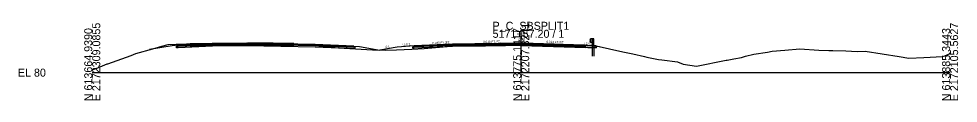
# Model space of a CAD drawing. Extents: x -26 to 1303, y -3010 to 12023.
# Drawn here: x -25.7 to 302.8, y -9.7 to 17.8 of the extents above; entities that cross this region are included whole.
import ezdxf

# ---------------------------------------------------------------- set-up
doc = ezdxf.new("R2010")
doc.units = 0
for name, color, linetype in [('RD_GPK_XS_Cell', 7, 'Continuous'), ('RD_PD_Final_TrvlWay', 7, 'Continuous'), ('RD_XS_Base', 7, 'Continuous'), ('RD_XS_Buildup', 7, 'Continuous'), ('RD_XS_ExGround', 7, 'Continuous'), ('RD_XS_ExPaveRet', 7, 'Continuous'), ('RD_XS_GR', 7, 'Continuous'), ('RD_XS_Greenside', 7, 'Continuous'), ('RD_XS_Pave', 7, 'Continuous'), ('RD_XS_PaveOvlay_CP', 7, 'Continuous'), ('RD_XS_TieSlope', 7, 'Continuous'), ('RD_XS_TX_Elev_EX', 7, 'Continuous'), ('RD_XS_TX_Elev_PR', 7, 'Continuous'), ('RD_XS_TX_ShdSlope', 7, 'Continuous'), ('RD_XS_TX_Slope', 7, 'Continuous')]:
    doc.layers.add(name, color=color, linetype=linetype)

msp = doc.modelspace()

# ---------------------------------------------------------------- linework, layer by layer
at = {"layer": 'RD_GPK_XS_Cell'}
for p, q in [((150, 0), (150, 15)), ((0, 0), (150, 0)), ((150, 0), (300, 0))]:
    msp.add_line(p, q, dxfattribs=at)
at = {"layer": 'RD_PD_Final_TrvlWay'}
for p, q in [((174.94, 5.78), (174.94, 9.38)), ((174.94, 9.38), (175.44, 9.34)), ((175.44, 9.34), (175.44, 5.78))]:
    msp.add_line(p, q, dxfattribs=at)
at = {"layer": 'RD_XS_Base'}
for p, q in [((42, 9.72), (54, 9.96)), ((54, 9.96), (54, 10.12)), ((54, 10.12), (54, 9.46)), ((54, 9.96), (54, 9.46)), ((78, 9.48), (54, 9.96)), ((54, 9.96), (54, 9.96)), ((126, 9.63), (150, 10.02)), ((150, 10.02), (150, 10.18)), ((150, 10.18), (150, 9.52)), ((150, 10.02), (150, 10.02)), ((172, 9.3), (150, 10.02)), ((150, 10.02), (150, 10.02)), ((150, 10.02), (150, 9.52)), ((29.5, 9.22), (30, 9.24)), ((29.5, 8.72), (29.5, 9.22)), ((29.5, 9.22), (29.5, 9.22)), ((30, 8.74), (29.5, 8.72)), ((29.5, 8.72), (29.5, 8.72)), ((29.5, 8.72), (29.5, 8.72)), ((30, 9.24), (42, 9.72)), ((30, 9.24), (30, 9.24)), ((42, 9.22), (30, 8.74)), ((30, 8.74), (30, 8.74)), ((42, 9.72), (42, 9.72)), ((54, 9.46), (42, 9.22)), ((42, 9.22), (42, 9.22)), ((54, 9.46), (54, 9.46)), ((54, 9.46), (54, 9.46)), ((54, 9.46), (78, 8.98)), ((91.44, 8.94), (78, 9.48)), ((78, 9.48), (78, 9.48)), ((78, 8.98), (78, 8.98)), ((78, 8.98), (91.94, 8.42)), ((91.94, 8.92), (91.44, 8.94)), ((91.44, 8.94), (91.44, 8.94)), ((91.94, 8.42), (91.94, 8.92)), ((91.94, 8.92), (91.94, 8.92)), ((91.94, 8.42), (91.94, 8.42)), ((91.94, 8.42), (91.94, 8.42)), ((112.13, 9.08), (112.63, 9.1)), ((112.13, 8.58), (112.13, 9.08)), ((112.13, 9.08), (112.13, 9.08)), ((112.63, 8.6), (112.13, 8.58)), ((112.13, 8.58), (112.13, 8.58)), ((112.13, 8.58), (112.13, 8.58)), ((112.63, 9.1), (126, 9.63)), ((126, 9.13), (112.63, 8.6)), ((112.63, 9.1), (112.63, 9.1)), ((112.63, 8.6), (112.63, 8.6)), ((150, 9.52), (126, 9.13)), ((149.99, 9.52), (172.5, 8.78)), ((150, 9.52), (150, 9.52)), ((150, 9.52), (150, 9.52)), ((172.5, 9.29), (172, 9.3)), ((172, 9.3), (172, 9.3)), ((172.5, 8.78), (172.5, 9.29)), ((172.5, 9.29), (172.5, 9.29)), ((172.5, 8.79), (172.5, 8.79)), ((172.5, 8.79), (172.5, 8.79))]:
    msp.add_line(p, q, dxfattribs=at)
at = {"layer": 'RD_XS_Buildup'}
msp.add_line((64, 10.28), (64, 10.26), dxfattribs=at)
at = {"layer": 'RD_XS_ExGround'}
msp.add_lwpolyline([(0, 1), (1.99, 1.68), (5.18, 3.04), (5.47, 3.09), (7.05, 3.69), (13.64, 6.05), (15.25, 6.73), (21.13, 8.38), (24.37, 9.28), (26.53, 9.89), (29.36, 10), (33, 10.13), (34.22, 10.12), (35.85, 10.14), (41.97, 10.15), (45.88, 10.2), (54.32, 10.28), (63.32, 10.27), (70.48, 10.23), (79.28, 9.35), (86.09, 8.72), (98.02, 8.04), (102.47, 7.81), (106.39, 8), (111.74, 8.25), (116.03, 8.45), (120.03, 8.83), (128.25, 9.53), (132.52, 9.98), (133.83, 10.08), (135.53, 10.1), (137.5, 10.14), (144.47, 10.25), (150.42, 10.35), (161.54, 9.96), (176.28, 9.44), (185.54, 7.24), (189.03, 6.58), (193.08, 5.61), (193.95, 5.43), (197.39, 4.72), (198.07, 4.64), (199.14, 4.44), (204.67, 3.75), (206.61, 3.01), (211.36, 2.29), (221.65, 4.31), (222.01, 4.32), (224.4, 4.87), (227.04, 5.35), (228.43, 5.74), (231.36, 6.48), (236.13, 7.18), (237.75, 7.47), (242.22, 7.88), (247.48, 8.29), (254.1, 7.87), (257.57, 7.72), (259, 7.72), (263.55, 7.62), (267.49, 7.44), (270.27, 7.46), (282.15, 5.66), (285.52, 5.1), (290.76, 5.35), (297.33, 5.67), (298.18, 5.94), (300, 6.67)], dxfattribs=at)
at = {"layer": 'RD_XS_ExPaveRet'}
for points in [[(70.48, 10.23), (70.48, 9.48), (70.48, 9.48), (70.48, 9.48), (70.48, 9.48), (63.32, 9.52), (63.32, 9.52), (54.32, 9.53), (45.88, 9.45), (45.88, 9.45), (41.97, 9.4), (41.97, 9.4), (41.97, 9.4), (35.85, 9.39), (35.85, 9.39), (34.22, 9.37), (34.22, 9.37), (34.22, 10.12), (35.85, 10.14), (35.85, 10.14), (41.97, 10.15), (41.97, 10.15), (41.97, 10.15), (45.88, 10.2), (45.88, 10.2), (54.32, 10.28), (63.32, 10.27), (63.32, 10.27), (70.48, 10.23), (70.48, 10.23), (70.48, 10.23)], [(70.48, 10.23), (63.32, 10.27), (54.32, 10.28), (45.88, 10.2), (41.97, 10.15), (35.85, 10.14), (34.22, 10.12), (34.22, 9.37), (35.85, 9.39), (41.97, 9.4), (45.88, 9.45), (54.32, 9.53), (63.32, 9.52), (70.48, 9.48), (70.48, 9.48), (70.48, 10.23), (70.48, 10.23)], [(176.28, 9.44), (176.28, 9.44), (176.28, 8.69), (176.28, 8.69), (176.28, 8.69), (161.54, 9.21), (161.54, 9.21), (150.42, 9.6), (144.47, 9.5), (144.47, 9.5), (137.5, 9.39), (137.5, 9.39), (135.53, 9.35), (133.83, 9.33), (133.83, 9.33), (133.83, 10.08), (135.53, 10.1), (137.5, 10.14), (137.5, 10.14), (144.47, 10.25), (144.47, 10.25), (150.42, 10.35), (161.54, 9.96), (161.54, 9.96), (176.28, 9.44)], [(161.54, 9.96), (150.42, 10.35), (144.47, 10.25), (137.5, 10.14), (135.53, 10.1), (133.83, 10.08), (133.83, 9.33), (135.53, 9.35), (137.5, 9.39), (144.47, 9.5), (150.42, 9.6), (161.54, 9.21), (176.28, 8.69), (176.28, 9.44), (161.54, 9.96)]]:
    msp.add_lwpolyline(points, dxfattribs=at)
at = {"layer": 'RD_XS_GR'}
for p, q in [((174, 11.49), (174.2, 11.7)), ((174.07, 11.41), (174, 11.49)), ((174, 10.9), (174.2, 11.12)), ((174.07, 10.83), (174, 10.9)), ((174.27, 11.19), (174.07, 11.41)), ((174.27, 10.61), (174.07, 10.83)), ((174.2, 11.7), (174.27, 11.78)), ((174.2, 11.12), (174.27, 11.19)), ((174.27, 11.78), (174.27, 10.61)), ((174.94, 11.78), (174.27, 11.78)), ((174.27, 11.78), (174.27, 11.47)), ((174.27, 11.47), (174.27, 10.61)), ((174.27, 10.61), (174.94, 10.61)), ((174.94, 11.78), (174.94, 9.38)), ((175.19, 11.78), (174.94, 11.78)), ((174.94, 10.61), (174.94, 11.78)), ((175.44, 11.78), (175.19, 11.78)), ((175.44, 9.34), (175.44, 11.78)), ((174.94, 9.38), (175.44, 9.34))]:
    msp.add_line(p, q, dxfattribs=at)
at = {"layer": 'RD_XS_Greenside'}
for p, q in [((28, 9.4), (19.99, 8.06)), ((93.44, 9.1), (100.52, 7.92)), ((106.63, 8.93), (100.52, 7.92))]:
    msp.add_line(p, q, dxfattribs=at)
at = {"layer": 'RD_XS_Pave'}
for p, q in [((42, 10.04), (30, 9.56)), ((42, 9.88), (30, 9.4)), ((30, 9.4), (42, 9.88)), ((54, 10.28), (42, 10.04)), ((54, 10.12), (42, 9.88)), ((42, 9.88), (54, 10.12)), ((42, 10.04), (42, 10.04)), ((42, 9.72), (54, 9.96)), ((42, 9.88), (42, 9.88)), ((42, 9.88), (42, 9.88)), ((78, 9.8), (54, 10.28)), ((54, 9.96), (54, 10.12)), ((54, 10.12), (78, 9.64)), ((78, 9.64), (54, 10.12)), ((54, 10.12), (54, 9.96)), ((54, 9.96), (54, 9.96)), ((54, 9.96), (54, 9.96)), ((54, 9.96), (78, 9.48)), ((126, 9.95), (112.63, 9.41)), ((150, 10.34), (126, 9.95)), ((150, 10.18), (126, 9.79)), ((126, 9.79), (150, 10.18)), ((126, 9.63), (150, 10.02)), ((172, 9.62), (150, 10.34)), ((150, 10.02), (150, 10.18)), ((150, 10.18), (172, 9.46)), ((172, 9.46), (150, 10.18)), ((150, 10.18), (150, 10.18)), ((150, 10.18), (150, 10.02)), ((150, 10.02), (150, 10.02)), ((150, 10.02), (150, 10.02)), ((150, 10.02), (150, 10.02)), ((150, 10.02), (172, 9.3)), ((30, 9.24), (42, 9.72)), ((30, 9.56), (30, 9.56)), ((30, 9.56), (30, 9.4)), ((30, 9.4), (30, 9.4)), ((30, 9.4), (30, 9.24)), ((30, 9.4), (30, 9.4)), ((30, 9.4), (30, 9.4)), ((30, 9.24), (30, 9.24)), ((30, 9.24), (30, 9.24)), ((42, 9.72), (42, 9.72)), ((91.44, 9.26), (78, 9.8)), ((78, 9.8), (78, 9.8)), ((78, 9.64), (78, 9.64)), ((78, 9.64), (91.44, 9.1)), ((91.44, 9.1), (78, 9.64)), ((78, 9.64), (78, 9.64)), ((78, 9.48), (78, 9.48)), ((78, 9.48), (91.44, 8.94)), ((91.44, 9.1), (91.44, 9.26)), ((91.44, 9.26), (91.44, 9.26)), ((91.44, 9.1), (91.44, 9.1)), ((91.44, 9.1), (91.44, 9.1)), ((91.44, 8.94), (91.44, 9.1)), ((91.44, 9.1), (91.44, 9.1)), ((91.44, 8.94), (91.44, 8.94)), ((91.44, 8.94), (91.44, 8.94)), ((126, 9.79), (112.63, 9.26)), ((112.63, 9.26), (126, 9.79)), ((112.63, 9.1), (126, 9.63)), ((112.63, 9.41), (112.63, 9.41)), ((112.63, 9.41), (112.63, 9.26)), ((112.63, 9.26), (112.63, 9.26)), ((112.63, 9.26), (112.63, 9.1)), ((112.63, 9.26), (112.63, 9.26)), ((112.63, 9.26), (112.63, 9.26)), ((112.63, 9.1), (112.63, 9.1)), ((112.63, 9.1), (112.63, 9.1)), ((172, 9.46), (172, 9.62)), ((172, 9.62), (172, 9.62)), ((172, 9.46), (172, 9.46)), ((172, 9.46), (172, 9.46)), ((172, 9.3), (172, 9.46)), ((172, 9.46), (172, 9.46)), ((172, 9.3), (172, 9.3)), ((172, 9.3), (172, 9.3))]:
    msp.add_line(p, q, dxfattribs=at)
at = {"layer": 'RD_XS_PaveOvlay_CP'}
for p, q in [((30, 9.56), (42, 10.04)), ((42, 10.04), (54, 10.28)), ((54, 10.28), (78, 9.8)), ((126, 9.95), (112.63, 9.41)), ((150, 10.34), (126, 9.95)), ((172, 9.62), (150, 10.34)), ((78, 9.8), (91.44, 9.26)), ((112.63, 9.41), (112.63, 9.41)), ((172, 9.62), (172, 9.62))]:
    msp.add_line(p, q, dxfattribs=at)
at = {"layer": 'RD_XS_TieSlope'}
for p, q in [((30, 9.56), (28, 9.4)), ((91.44, 9.26), (93.44, 9.1)), ((112.63, 9.41), (106.63, 8.93)), ((172, 9.62), (177.34, 9.19))]:
    msp.add_line(p, q, dxfattribs=at)

# ---------------------------------------------------------------- texts
at = {"layer": 'RD_GPK_XS_Cell'}
for s, p in [('E 2172309.0855', (2.8, -10)), ('E 2172207.3241', (152.8, -10)), ('E 2172105.5627', (302.8, -10)), ('N 613664.9390', (0, -10)), ('N 613775.1417', (150, -10)), ('N 613885.3443', (300, -10))]:
    msp.add_text(s, height=2.8, rotation=90, dxfattribs=at).set_placement(p)
for s, p in [('P_C_SBSPLIT1', (140, 15)), ('5171+57.20 / 1', (140, 12.2)), ('EL 80', (-26, -1.4))]:
    msp.add_text(s, height=2.8, dxfattribs=at).set_placement(p)
at = {"layer": 'RD_XS_TX_Elev_EX'}
msp.add_text('90.34', height=0.6, rotation=90, dxfattribs=at).set_placement((149.65, 11.02))
at = {"layer": 'RD_XS_TX_Elev_PR'}
msp.add_text('90.34', height=1, rotation=90, dxfattribs=at).set_placement((151.35, 10.68))
at = {"layer": 'RD_XS_TX_ShdSlope'}
for rotation, p in [(4.5739, (108.4, 9.38)), (355.4261, (171.97, 9.9))]:
    msp.add_text('12.5:1', height=0.75, rotation=rotation, dxfattribs=at).set_placement(p)
at = {"layer": 'RD_XS_TX_Slope'}
for s, rotation, p in [('0.040 FT./FT.', 2.2906, (118.93, 9.97)), ('0.016 FT./FT.', 0.4422, (136.69, 10.4)), ('0.033 FT./FT.', 358.8542, (158.85, 10.42)), ('6:1', 9.4642, (102.6, 8.63))]:
    msp.add_text(s, height=0.75, rotation=rotation, dxfattribs=at).set_placement(p)

doc.saveas('drawing.dxf')
